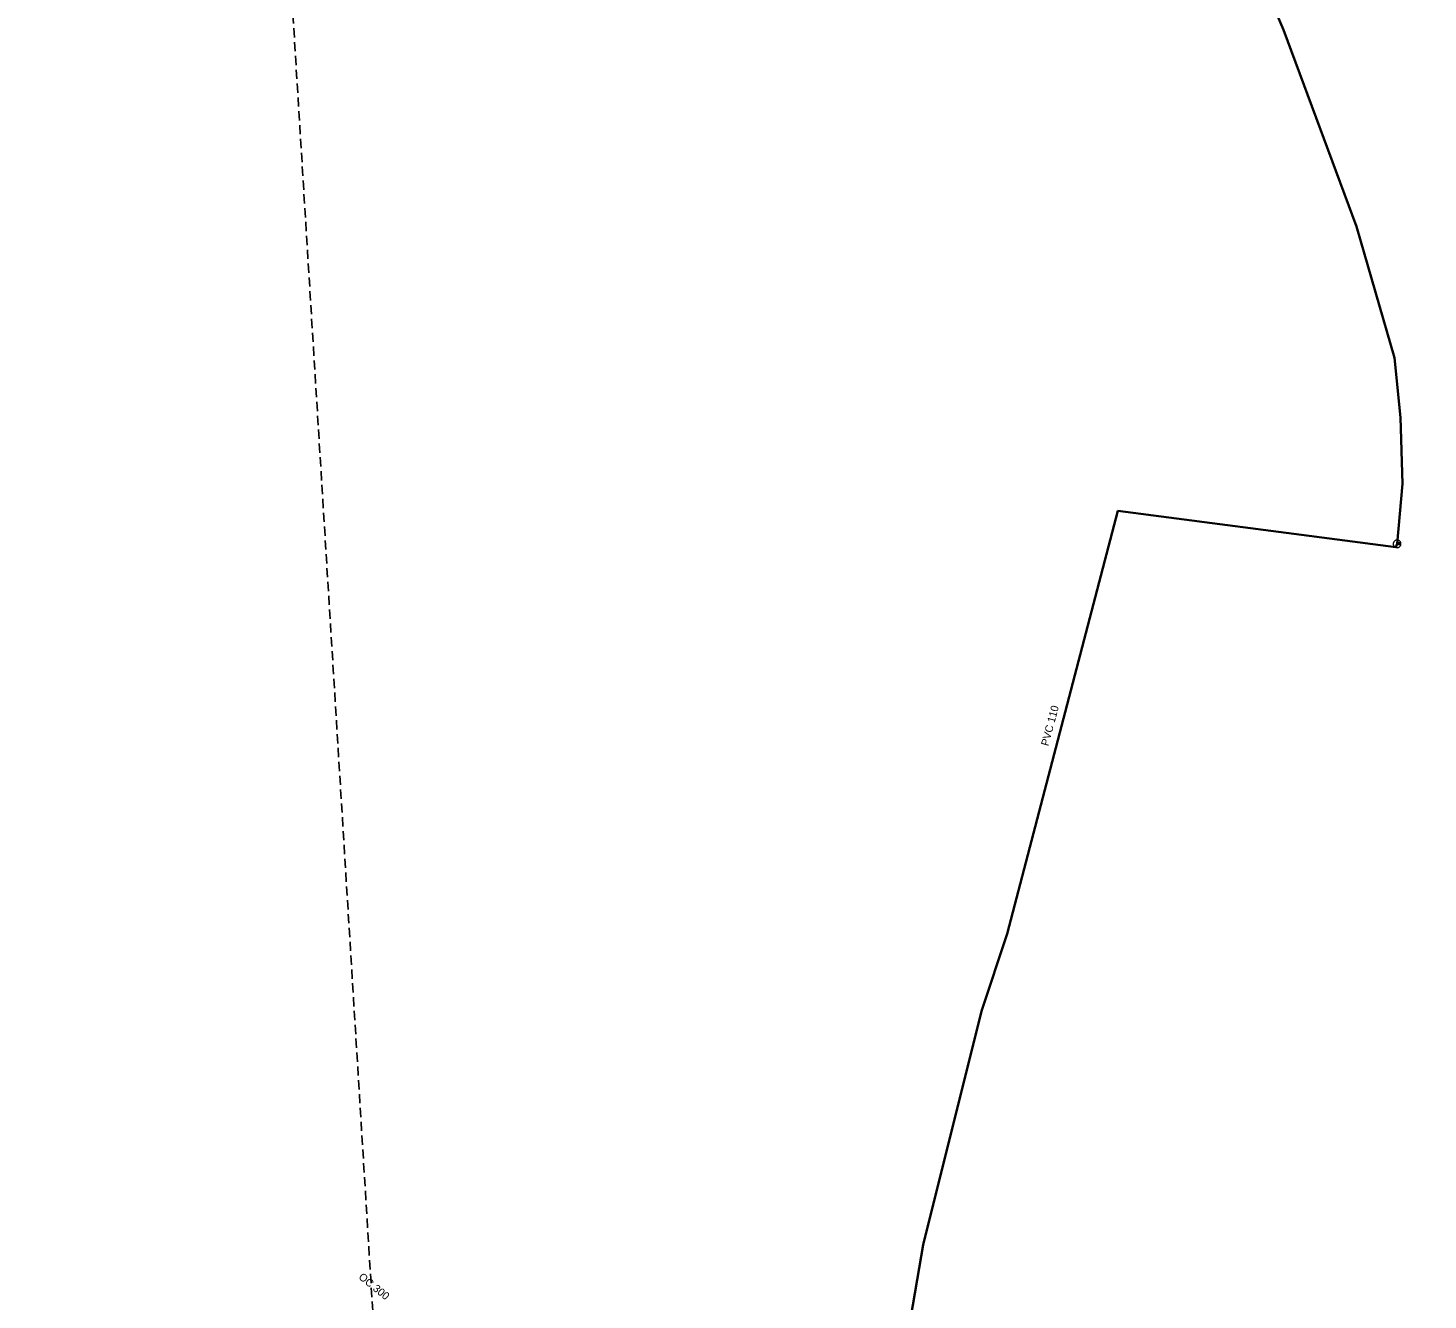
# Model space of a CAD drawing. Extents: x -724325 to -723665, y -972119 to -970722.
# Drawn here: x -723995.2 to -723813.5, y -971585.6 to -971420.5 of the extents above; entities that cross this region are included whole.
import ezdxf

# ---------------------------------------------------------------- set-up
doc = ezdxf.new("R2010")
doc.units = 0
doc.header["$LTSCALE"] = 0.4
doc.linetypes.add('MEDIUM_DASHED', pattern=[4.5, 3, -1.5])
for name, color, linetype, lineweight in [('1', 7, 'Continuous', 25), ('14', 7, 'Continuous', 25), ('17', 7, 'Continuous', 35), ('47', 7, 'Continuous', 13), ('9', 7, 'Continuous', 13)]:
    doc.layers.add(name, color=color, linetype=linetype, lineweight=lineweight)

msp = doc.modelspace()

# ---------------------------------------------------------------- linework, layer by layer
at = {"layer": '1', "linetype": 'MEDIUM_DASHED'}
msp.add_lwpolyline([(-724178.033, -970726.408), (-723849.368, -970722.221), (-723876.582, -971170.211), (-723665.148, -971503.063), (-723686.082, -972118.833), (-723917.752, -972118.833), (-723962.412, -971393.118), (-724325.27, -971133.535)], close=True, dxfattribs=at)
at = {"layer": '14', "lineweight": 13}
msp.add_line((-723817.559, -971487.479), (-723817.31, -971487.459), dxfattribs=at)
at = {"layer": '17'}
for points in [[(-723897.32, -971301.379), (-723897.12, -971301.809), (-723878.899, -971335.289), (-723856.64, -971370.239), (-723846.059, -971388.75), (-723832.309, -971420.76), (-723822.829, -971446.28), (-723817.91, -971463.35), (-723817.129, -971471.1), (-723816.85, -971479.71), (-723817.559, -971487.479)], [(-723817.559, -971487.479), (-723817.73, -971487.899), (-723853.789, -971483.199), (-723868.17, -971538.109), (-723871.489, -971548.129), (-723879.039, -971578.469), (-723880.91, -971589.34), (-723881.28, -971597.94), (-723874.359, -971626.71), (-723870.739, -971639.129), (-723857.901, -971672.82), (-723852.42, -971690.039), (-723848.03, -971707.579), (-723845.87, -971728.859), (-723846.129, -971731.379), (-723847.35, -971737.449), (-723847.89, -971765.809), (-723847.93, -971768.44), (-723847.48, -971775.98)]]:
    msp.add_lwpolyline(points, dxfattribs=at)
at = {"layer": '47'}
for points in [[(-723817.537, -971487.978), (-723817.485, -971487.973), (-723817.434, -971487.963), (-723817.384, -971487.947), (-723817.336, -971487.926), (-723817.29, -971487.9), (-723817.248, -971487.87), (-723817.209, -971487.835), (-723817.174, -971487.796), (-723817.142, -971487.755), (-723817.115, -971487.71), (-723817.093, -971487.662), (-723817.077, -971487.612), (-723817.066, -971487.562), (-723817.06, -971487.509), (-723817.059, -971487.457), (-723817.064, -971487.405), (-723817.074, -971487.354), (-723817.091, -971487.303), (-723817.111, -971487.256), (-723817.137, -971487.21), (-723817.167, -971487.168), (-723817.202, -971487.128), (-723817.241, -971487.093), (-723817.282, -971487.061), (-723817.327, -971487.035), (-723817.375, -971487.013), (-723817.425, -971486.996), (-723817.475, -971486.986), (-723817.528, -971486.98), (-723817.58, -971486.979), (-723817.632, -971486.984), (-723817.683, -971486.994), (-723817.734, -971487.01), (-723817.781, -971487.031), (-723817.827, -971487.057), (-723817.869, -971487.086), (-723817.909, -971487.121), (-723817.944, -971487.16), (-723817.976, -971487.202), (-723818.002, -971487.247), (-723818.024, -971487.295), (-723818.041, -971487.344), (-723818.051, -971487.395), (-723818.057, -971487.448), (-723818.058, -971487.5), (-723818.053, -971487.552), (-723818.043, -971487.603), (-723818.028, -971487.653), (-723818.006, -971487.701), (-723817.98, -971487.747), (-723817.951, -971487.789), (-723817.916, -971487.828), (-723817.877, -971487.863), (-723817.835, -971487.895), (-723817.79, -971487.922), (-723817.742, -971487.944), (-723817.693, -971487.96), (-723817.642, -971487.971), (-723817.589, -971487.977)], [(-723817.555, -971487.56), (-723817.546, -971487.56), (-723817.538, -971487.558), (-723817.53, -971487.555), (-723817.522, -971487.552), (-723817.515, -971487.548), (-723817.508, -971487.542), (-723817.501, -971487.537), (-723817.495, -971487.531), (-723817.491, -971487.524), (-723817.486, -971487.516), (-723817.482, -971487.508), (-723817.48, -971487.5), (-723817.478, -971487.492), (-723817.476, -971487.484), (-723817.477, -971487.475), (-723817.477, -971487.466), (-723817.479, -971487.458), (-723817.482, -971487.45), (-723817.485, -971487.442), (-723817.489, -971487.435), (-723817.495, -971487.428), (-723817.5, -971487.421), (-723817.506, -971487.415), (-723817.513, -971487.41), (-723817.521, -971487.406), (-723817.529, -971487.402), (-723817.537, -971487.4), (-723817.545, -971487.398), (-723817.553, -971487.396), (-723817.562, -971487.397), (-723817.571, -971487.397), (-723817.579, -971487.399), (-723817.587, -971487.402), (-723817.595, -971487.405), (-723817.602, -971487.409), (-723817.609, -971487.414), (-723817.616, -971487.42), (-723817.622, -971487.426), (-723817.627, -971487.433), (-723817.631, -971487.441), (-723817.635, -971487.449), (-723817.637, -971487.457), (-723817.639, -971487.465), (-723817.641, -971487.473), (-723817.64, -971487.482), (-723817.64, -971487.491), (-723817.638, -971487.499), (-723817.635, -971487.507), (-723817.632, -971487.515), (-723817.628, -971487.522), (-723817.623, -971487.529), (-723817.617, -971487.536), (-723817.611, -971487.542), (-723817.604, -971487.546), (-723817.596, -971487.551), (-723817.588, -971487.555), (-723817.58, -971487.557), (-723817.572, -971487.559), (-723817.564, -971487.561)]]:
    msp.add_lwpolyline(points, close=True, dxfattribs=at)
at = {"layer": '9'}
for points in [[(-723817.436, -971487.459), (-723817.436, -971487.472), (-723817.434, -971487.485), (-723817.431, -971487.498), (-723817.426, -971487.51), (-723817.42, -971487.522), (-723817.413, -971487.533), (-723817.405, -971487.543), (-723817.395, -971487.553), (-723817.385, -971487.561), (-723817.374, -971487.568), (-723817.362, -971487.574), (-723817.35, -971487.579), (-723817.337, -971487.582), (-723817.324, -971487.584), (-723817.311, -971487.586), (-723817.298, -971487.585), (-723817.285, -971487.583), (-723817.272, -971487.58), (-723817.26, -971487.575), (-723817.248, -971487.569), (-723817.237, -971487.562), (-723817.227, -971487.554), (-723817.217, -971487.544), (-723817.209, -971487.534), (-723817.202, -971487.523), (-723817.196, -971487.511), (-723817.191, -971487.499), (-723817.188, -971487.486), (-723817.186, -971487.473), (-723817.184, -971487.46), (-723817.185, -971487.447), (-723817.187, -971487.434), (-723817.19, -971487.421), (-723817.195, -971487.409), (-723817.201, -971487.397), (-723817.208, -971487.386), (-723817.216, -971487.376), (-723817.226, -971487.366), (-723817.236, -971487.358), (-723817.247, -971487.351), (-723817.259, -971487.345), (-723817.271, -971487.34), (-723817.284, -971487.337), (-723817.297, -971487.335), (-723817.31, -971487.334), (-723817.323, -971487.334), (-723817.336, -971487.336), (-723817.349, -971487.339), (-723817.361, -971487.344), (-723817.373, -971487.35), (-723817.384, -971487.357), (-723817.394, -971487.365), (-723817.404, -971487.375), (-723817.412, -971487.385), (-723817.419, -971487.396), (-723817.425, -971487.408), (-723817.43, -971487.42), (-723817.433, -971487.433), (-723817.435, -971487.446)], [(-723817.416, -971487.459), (-723817.417, -971487.47), (-723817.415, -971487.481), (-723817.412, -971487.492), (-723817.408, -971487.502), (-723817.403, -971487.512), (-723817.397, -971487.521), (-723817.39, -971487.53), (-723817.382, -971487.538), (-723817.373, -971487.545), (-723817.364, -971487.551), (-723817.354, -971487.556), (-723817.344, -971487.56), (-723817.333, -971487.563), (-723817.322, -971487.566), (-723817.311, -971487.566), (-723817.3, -971487.566), (-723817.289, -971487.564), (-723817.278, -971487.561), (-723817.268, -971487.557), (-723817.258, -971487.552), (-723817.249, -971487.546), (-723817.24, -971487.539), (-723817.232, -971487.531), (-723817.225, -971487.522), (-723817.219, -971487.513), (-723817.214, -971487.503), (-723817.21, -971487.493), (-723817.207, -971487.482), (-723817.205, -971487.471), (-723817.204, -971487.46), (-723817.204, -971487.449), (-723817.206, -971487.438), (-723817.209, -971487.427), (-723817.213, -971487.417), (-723817.218, -971487.407), (-723817.224, -971487.398), (-723817.231, -971487.389), (-723817.239, -971487.381), (-723817.248, -971487.374), (-723817.257, -971487.368), (-723817.267, -971487.363), (-723817.277, -971487.359), (-723817.288, -971487.356), (-723817.299, -971487.354), (-723817.31, -971487.354), (-723817.321, -971487.353), (-723817.332, -971487.355), (-723817.343, -971487.358), (-723817.353, -971487.362), (-723817.363, -971487.367), (-723817.372, -971487.373), (-723817.381, -971487.38), (-723817.389, -971487.388), (-723817.396, -971487.397), (-723817.402, -971487.406), (-723817.407, -971487.416), (-723817.411, -971487.426), (-723817.414, -971487.437), (-723817.416, -971487.448)], [(-723817.397, -971487.459), (-723817.397, -971487.468), (-723817.396, -971487.477), (-723817.393, -971487.486), (-723817.39, -971487.494), (-723817.386, -971487.502), (-723817.381, -971487.51), (-723817.375, -971487.517), (-723817.369, -971487.523), (-723817.362, -971487.529), (-723817.354, -971487.534), (-723817.346, -971487.538), (-723817.338, -971487.541), (-723817.329, -971487.544), (-723817.32, -971487.545), (-723817.311, -971487.547), (-723817.302, -971487.546), (-723817.293, -971487.545), (-723817.284, -971487.542), (-723817.276, -971487.539), (-723817.268, -971487.535), (-723817.26, -971487.53), (-723817.253, -971487.524), (-723817.247, -971487.518), (-723817.241, -971487.511), (-723817.236, -971487.503), (-723817.232, -971487.495), (-723817.229, -971487.487), (-723817.226, -971487.478), (-723817.225, -971487.469), (-723817.223, -971487.46), (-723817.224, -971487.451), (-723817.225, -971487.442), (-723817.228, -971487.433), (-723817.231, -971487.425), (-723817.235, -971487.417), (-723817.24, -971487.409), (-723817.246, -971487.402), (-723817.252, -971487.396), (-723817.259, -971487.39), (-723817.267, -971487.385), (-723817.275, -971487.381), (-723817.283, -971487.378), (-723817.292, -971487.375), (-723817.301, -971487.374), (-723817.31, -971487.373), (-723817.319, -971487.373), (-723817.328, -971487.374), (-723817.337, -971487.377), (-723817.345, -971487.38), (-723817.353, -971487.384), (-723817.361, -971487.389), (-723817.368, -971487.395), (-723817.374, -971487.401), (-723817.38, -971487.408), (-723817.385, -971487.416), (-723817.389, -971487.424), (-723817.392, -971487.432), (-723817.395, -971487.441), (-723817.396, -971487.45)], [(-723817.377, -971487.459), (-723817.377, -971487.466), (-723817.376, -971487.473), (-723817.375, -971487.48), (-723817.372, -971487.486), (-723817.369, -971487.492), (-723817.365, -971487.498), (-723817.361, -971487.504), (-723817.356, -971487.509), (-723817.35, -971487.513), (-723817.344, -971487.517), (-723817.338, -971487.52), (-723817.332, -971487.523), (-723817.325, -971487.524), (-723817.318, -971487.527), (-723817.311, -971487.527), (-723817.304, -971487.527), (-723817.297, -971487.525), (-723817.29, -971487.524), (-723817.284, -971487.521), (-723817.277, -971487.518), (-723817.272, -971487.514), (-723817.266, -971487.51), (-723817.261, -971487.505), (-723817.257, -971487.499), (-723817.253, -971487.493), (-723817.25, -971487.487), (-723817.247, -971487.481), (-723817.245, -971487.474), (-723817.244, -971487.467), (-723817.243, -971487.46), (-723817.243, -971487.453), (-723817.244, -971487.446), (-723817.246, -971487.439), (-723817.249, -971487.433), (-723817.252, -971487.426), (-723817.256, -971487.421), (-723817.26, -971487.415), (-723817.265, -971487.41), (-723817.271, -971487.406), (-723817.276, -971487.402), (-723817.283, -971487.399), (-723817.289, -971487.396), (-723817.296, -971487.394), (-723817.303, -971487.393), (-723817.31, -971487.393), (-723817.317, -971487.393), (-723817.324, -971487.393), (-723817.331, -971487.395), (-723817.337, -971487.398), (-723817.343, -971487.401), (-723817.349, -971487.405), (-723817.355, -971487.409), (-723817.36, -971487.414), (-723817.364, -971487.42), (-723817.368, -971487.425), (-723817.371, -971487.432), (-723817.374, -971487.438), (-723817.375, -971487.445), (-723817.377, -971487.452)], [(-723817.357, -971487.459), (-723817.357, -971487.464), (-723817.357, -971487.469), (-723817.356, -971487.474), (-723817.354, -971487.478), (-723817.352, -971487.483), (-723817.349, -971487.487), (-723817.346, -971487.49), (-723817.342, -971487.494), (-723817.339, -971487.497), (-723817.335, -971487.5), (-723817.33, -971487.502), (-723817.326, -971487.504), (-723817.321, -971487.505), (-723817.316, -971487.507), (-723817.311, -971487.507), (-723817.306, -971487.507), (-723817.301, -971487.506), (-723817.296, -971487.505), (-723817.292, -971487.503), (-723817.287, -971487.501), (-723817.283, -971487.498), (-723817.279, -971487.495), (-723817.276, -971487.491), (-723817.273, -971487.488), (-723817.27, -971487.484), (-723817.268, -971487.479), (-723817.266, -971487.475), (-723817.265, -971487.47), (-723817.264, -971487.465), (-723817.263, -971487.46), (-723817.263, -971487.455), (-723817.264, -971487.45), (-723817.265, -971487.445), (-723817.267, -971487.441), (-723817.269, -971487.436), (-723817.272, -971487.432), (-723817.275, -971487.428), (-723817.278, -971487.425), (-723817.282, -971487.422), (-723817.286, -971487.419), (-723817.291, -971487.417), (-723817.295, -971487.415), (-723817.3, -971487.414), (-723817.305, -971487.413), (-723817.31, -971487.413), (-723817.315, -971487.413), (-723817.32, -971487.414), (-723817.325, -971487.414), (-723817.329, -971487.416), (-723817.334, -971487.418), (-723817.338, -971487.421), (-723817.341, -971487.424), (-723817.345, -971487.427), (-723817.348, -971487.431), (-723817.351, -971487.435), (-723817.353, -971487.44), (-723817.355, -971487.444), (-723817.356, -971487.449), (-723817.357, -971487.454)], [(-723817.337, -971487.459), (-723817.337, -971487.462), (-723817.338, -971487.465), (-723817.337, -971487.467), (-723817.336, -971487.47), (-723817.335, -971487.473), (-723817.333, -971487.475), (-723817.331, -971487.477), (-723817.329, -971487.479), (-723817.327, -971487.481), (-723817.325, -971487.483), (-723817.322, -971487.485), (-723817.319, -971487.486), (-723817.317, -971487.486), (-723817.314, -971487.487), (-723817.311, -971487.487), (-723817.308, -971487.487), (-723817.305, -971487.487), (-723817.302, -971487.486), (-723817.3, -971487.485), (-723817.297, -971487.484), (-723817.295, -971487.482), (-723817.292, -971487.48), (-723817.29, -971487.478), (-723817.289, -971487.476), (-723817.287, -971487.474), (-723817.286, -971487.471), (-723817.284, -971487.468), (-723817.284, -971487.466), (-723817.283, -971487.463), (-723817.282, -971487.46), (-723817.283, -971487.457), (-723817.283, -971487.454), (-723817.284, -971487.451), (-723817.285, -971487.449), (-723817.286, -971487.446), (-723817.288, -971487.444), (-723817.289, -971487.441), (-723817.291, -971487.439), (-723817.294, -971487.438), (-723817.296, -971487.436), (-723817.299, -971487.435), (-723817.301, -971487.434), (-723817.304, -971487.433), (-723817.307, -971487.433), (-723817.31, -971487.432), (-723817.313, -971487.433), (-723817.316, -971487.432), (-723817.318, -971487.434), (-723817.321, -971487.434), (-723817.324, -971487.435), (-723817.326, -971487.437), (-723817.328, -971487.438), (-723817.33, -971487.44), (-723817.332, -971487.443), (-723817.334, -971487.445), (-723817.335, -971487.448), (-723817.336, -971487.45), (-723817.337, -971487.453), (-723817.337, -971487.456)], [(-723817.318, -971487.459), (-723817.318, -971487.461), (-723817.318, -971487.461), (-723817.317, -971487.461), (-723817.317, -971487.463), (-723817.318, -971487.464), (-723817.316, -971487.464), (-723817.316, -971487.464), (-723817.316, -971487.466), (-723817.316, -971487.466), (-723817.315, -971487.467), (-723817.313, -971487.467), (-723817.313, -971487.467), (-723817.313, -971487.468), (-723817.311, -971487.468), (-723817.311, -971487.468), (-723817.31, -971487.468), (-723817.309, -971487.468), (-723817.309, -971487.467), (-723817.308, -971487.467), (-723817.306, -971487.467), (-723817.306, -971487.466), (-723817.306, -971487.466), (-723817.305, -971487.465), (-723817.305, -971487.465), (-723817.303, -971487.464), (-723817.303, -971487.463), (-723817.302, -971487.462), (-723817.302, -971487.462), (-723817.302, -971487.461), (-723817.302, -971487.46), (-723817.302, -971487.459), (-723817.302, -971487.458), (-723817.302, -971487.458), (-723817.303, -971487.457), (-723817.303, -971487.456), (-723817.304, -971487.455), (-723817.304, -971487.455), (-723817.305, -971487.454), (-723817.305, -971487.454), (-723817.306, -971487.453), (-723817.307, -971487.453), (-723817.308, -971487.452), (-723817.308, -971487.452), (-723817.309, -971487.452), (-723817.31, -971487.452), (-723817.311, -971487.452), (-723817.312, -971487.452), (-723817.312, -971487.452), (-723817.313, -971487.453), (-723817.314, -971487.452), (-723817.315, -971487.454), (-723817.315, -971487.454), (-723817.316, -971487.454), (-723817.316, -971487.454), (-723817.317, -971487.456), (-723817.317, -971487.457), (-723817.317, -971487.458), (-723817.318, -971487.458), (-723817.318, -971487.459)]]:
    msp.add_lwpolyline(points, close=True, dxfattribs=at)

# ---------------------------------------------------------------- texts
at = {"layer": '1'}
for s, rotation, p in [('PVC 110 ', 75, (-723862.819, -971513.79)), ('OC 300', 321, (-723952.4, -971582.793))]:
    msp.add_text(s, height=1, rotation=rotation, dxfattribs=at).set_placement(p)

doc.saveas('drawing.dxf')
